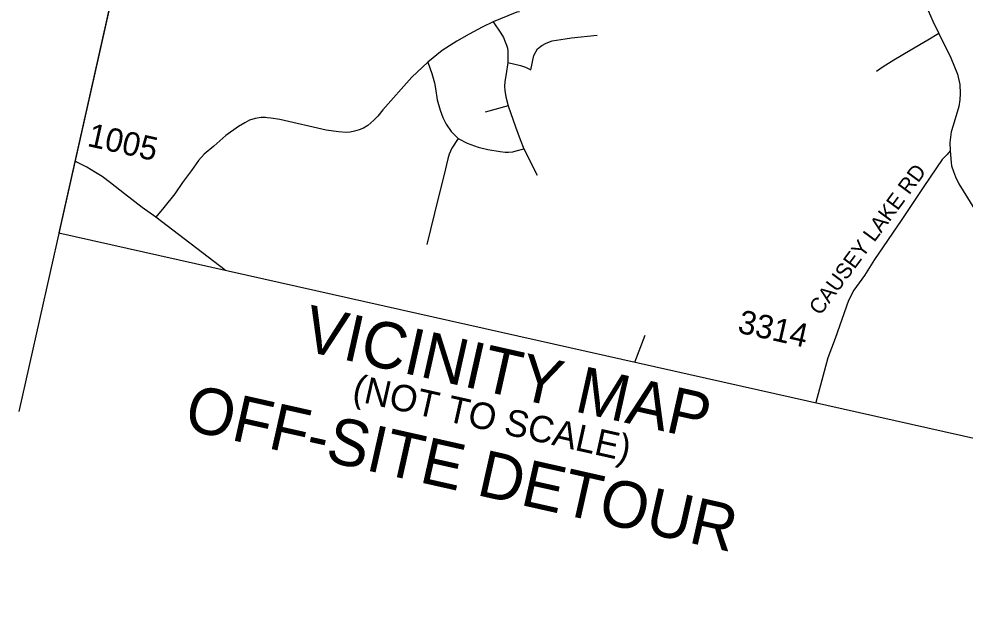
# Model space of a CAD drawing. Extents: x 1784499 to 1786147, y 841097 to 842538.
# Drawn here: x 1784498.9 to 1784767.1, y 841976.5 to 842146.6 of the extents above; entities that cross this region are included whole.
import ezdxf

# ---------------------------------------------------------------- set-up
doc = ezdxf.new("R2010")
doc.units = 0
for name, color, linetype in [('Exist Road Secondary Type 51 Attributed', 7, 'Continuous'), ('Exist Road Secondary Type 51 Number Label', 7, 'Continuous'), ('Old_Level_40', 7, 'Continuous'), ('Old_Level_42', 7, 'Continuous'), ('Old_Level_59', 7, 'Continuous'), ('Prop DSN Text', 7, 'Continuous'), ('Scratch_Level_3', 7, 'Continuous')]:
    doc.layers.add(name, color=color, linetype=linetype)

msp = doc.modelspace()

# ---------------------------------------------------------------- linework, layer by layer
at = {"layer": 'Exist Road Secondary Type 51 Attributed'}
for p, q in [((1784637.6, 842122.02), (1784631.03, 842120.21)), ((1784642.03, 842109.76), (1784645.75, 842102.31))]:
    msp.add_line(p, q, dxfattribs=at)
for points in [[(1784753.8, 842155.56), (1784755.99, 842150.5), (1784757.99, 842145.97), (1784759.68, 842142.46)], [(1784640.81, 842148.57), (1784640.05, 842148.48), (1784637.52, 842147.48), (1784633.29, 842145.81)], [(1784633.29, 842145.81), (1784630.2, 842144.3), (1784626.49, 842142.31), (1784622.98, 842140.28), (1784618.83, 842137.65), (1784614.82, 842134.31)], [(1784633.29, 842145.81), (1784635.45, 842142.53), (1784636.2, 842141.3), (1784636.75, 842140.09), (1784637.13, 842139.18), (1784637.37, 842138.28), (1784637.43, 842137.48), (1784637.46, 842136.29), (1784637.46, 842134.29)], [(1784644.03, 842132.16), (1784644.86, 842136.28), (1784645.88, 842138.17), (1784647.07, 842139.08), (1784648.35, 842139.77), (1784650.07, 842140.42), (1784652.51, 842140.76), (1784655.56, 842141.21), (1784662.78, 842142.04)], [(1784759.68, 842142.46), (1784756.54, 842140.63), (1784751.51, 842137.62), (1784746.93, 842134.94), (1784743.86, 842132.99), (1784741.94, 842131.69)], [(1784759.68, 842142.46), (1784763.05, 842135.59), (1784764.92, 842130.92), (1784765.61, 842128.04), (1784765.73, 842125.49), (1784765.58, 842123.69), (1784765.35, 842121.81), (1784763.7, 842116.43), (1784763.1, 842114.57), (1784762.78, 842111.56), (1784762.82, 842109.22)], [(1784614.82, 842134.31), (1784610.22, 842130.09), (1784602, 842120.83), (1784600.61, 842119.07), (1784599.47, 842117.89), (1784597.77, 842116.38), (1784596.53, 842115.68), (1784595.36, 842115.15), (1784593.99, 842114.78), (1784592.79, 842114.53), (1784591.66, 842114.45), (1784589.45, 842114.57), (1784585.99, 842115.12), (1784572.88, 842118.06), (1784570.32, 842118.48), (1784569.3, 842118.62), (1784568.82, 842118.66), (1784567.55, 842118.64), (1784565.85, 842118.34), (1784564.28, 842117.87), (1784562.88, 842117.13), (1784561.14, 842116.1), (1784557.55, 842113.56), (1784554.11, 842110.54), (1784551.44, 842108.25), (1784549.75, 842106.46), (1784547.85, 842103.66), (1784545.24, 842100.23), (1784543.07, 842097.04), (1784539.99, 842093.2), (1784537.72, 842090.44)], [(1784614.82, 842134.31), (1784615.94, 842131.1), (1784616.66, 842128.47), (1784616.99, 842126.93), (1784617.42, 842123.7), (1784618.27, 842120.74), (1784619.02, 842118.68), (1784619.99, 842116.74), (1784621.42, 842114.69), (1784623.44, 842112.76)], [(1784637.46, 842134.29), (1784636.97, 842131.08), (1784636.66, 842128.9), (1784636.55, 842127.5), (1784636.59, 842126.28), (1784636.94, 842124.57), (1784637.6, 842122.02)], [(1784637.46, 842134.29), (1784641.03, 842133.36), (1784642.51, 842132.93), (1784644.03, 842132.16)], [(1784637.6, 842122.02), (1784639.68, 842116.05), (1784640.98, 842112.39), (1784642.03, 842109.76)], [(1784623.44, 842112.76), (1784621.64, 842110), (1784620.86, 842108.25), (1784620.42, 842106.97), (1784619.42, 842102.5), (1784617.68, 842095.81), (1784614.51, 842082.67)], [(1784623.44, 842112.76), (1784625.92, 842111.43), (1784629.05, 842110.27), (1784631.84, 842109.64), (1784635.34, 842109.01), (1784636.7, 842108.86), (1784637.62, 842108.86), (1784638.92, 842108.93), (1784639.85, 842109.18), (1784642.03, 842109.76)], [(1784762.82, 842109.22), (1784761.98, 842108.22), (1784760.63, 842106.76)], [(1784762.82, 842109.22), (1784763.16, 842105.92), (1784763.27, 842104.98), (1784763.81, 842103.37), (1784764.37, 842101.84), (1784765.35, 842099.86), (1784767.74, 842095.87), (1784772.63, 842088.07)], [(1784537.72, 842090.44), (1784533.82, 842093.19), (1784528.81, 842097.08), (1784524.83, 842100.11), (1784522.44, 842101.93), (1784520.61, 842103.08), (1784518.12, 842104.56), (1784515.68, 842105.85), (1784514.79, 842106.32)], [(1784760.63, 842106.76), (1784755.43, 842099.12), (1784749.01, 842089.48), (1784741.43, 842078.45), (1784738.56, 842073.88), (1784735.54, 842069.72), (1784734.02, 842066.84), (1784730.23, 842056.03), (1784728.19, 842050.56), (1784724.77, 842037.95), (1784724.74, 842037.88)], [(1784557.32, 842075.42), (1784537.72, 842090.44)], [(1784673.51, 842049.37), (1784676.44, 842057.03)]]:
    msp.add_lwpolyline(points, dxfattribs=at)
at = {"layer": 'Old_Level_40'}
msp.add_line((1784611.59, 842537.98), (1784498.88, 842035.39), dxfattribs=at)
at = {"layer": 'Scratch_Level_3'}
msp.add_lwpolyline([(1785039.41, 842390.83), (1785050.23, 842439.1), (1784611.48, 842537.49), (1784510.23, 842085.98), (1784998.27, 841976.54), (1785088.7, 842379.78)], close=True, dxfattribs=at)

# ---------------------------------------------------------------- texts
at = {"layer": 'Exist Road Secondary Type 51 Number Label'}
for s, p in [('1005', (1784518, 842110.64)), ('3314', (1784702.34, 842057.78))]:
    msp.add_text(s, height=6.665, rotation=347.3599, dxfattribs=at).set_placement(p)
at = {"layer": 'Old_Level_40'}
msp.add_text('(NOT TO SCALE)', height=7.5068, rotation=347.3599, dxfattribs=at).set_placement((1784593.06, 842038.65))
at = {"layer": 'Old_Level_42'}
msp.add_text('VICINITY MAP', height=13.1537, rotation=347.3599, dxfattribs=at).set_placement((1784578.79, 842052.79))
at = {"layer": 'Old_Level_59'}
msp.add_text('OFF-SITE DETOUR', height=13.1537, rotation=347.3595, dxfattribs=at).set_placement((1784545.32, 842030.36))
at = {"layer": 'Prop DSN Text'}
msp.add_text('CAUSEY LAKE RD', height=4.3971, rotation=53.5971, dxfattribs=at).set_placement((1784726.03, 842062.35))

doc.saveas('drawing.dxf')
